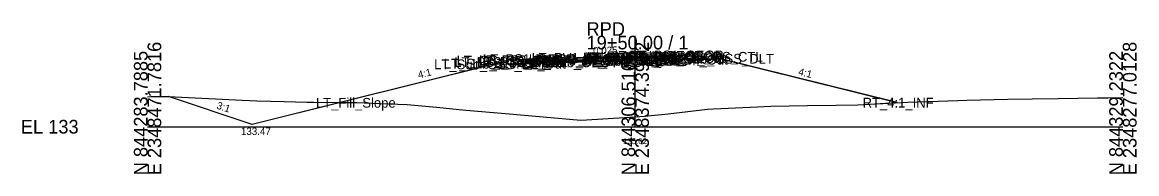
# Model space of a CAD drawing. Extents: x -26 to 2348536, y -510 to 844755.
# Drawn here: x -25.7 to 202.8, y 4490.3 to 4521.5 of the extents above; entities that cross this region are included whole.
import ezdxf

# ---------------------------------------------------------------- set-up
doc = ezdxf.new("R2010")
doc.units = 0
for name, color, linetype in [('Default', 7, 'Continuous'), ('Exist Cross Section Cell', 7, 'Continuous'), ('Exist XS Center Line Elevation Label', 7, 'Continuous'), ('Exist XS Ground Line', 7, 'Continuous'), ('Prop CMT Pvmt Course 1', 7, 'Continuous'), ('Prop CMT Pvmt Course 2', 7, 'Continuous'), ('Prop CMT Pvmt Course 3', 7, 'Continuous'), ('Prop CMT Pvmt Surface', 7, 'Continuous'), ('Prop CMT Pvmt Surface Shoulder', 7, 'Continuous'), ('Prop CMT Shld Paved Course 1', 7, 'Continuous'), ('Prop CMT Shld Paved Course 2', 7, 'Continuous'), ('Prop CMT Shld Paved Course 3', 7, 'Continuous'), ('Prop CMT Slope Grass', 7, 'Continuous'), ('Prop CMT Subgrade Earthwork', 7, 'Continuous'), ('Prop XS Ditch Standard Text', 7, 'Continuous'), ('Prop XS Earthwork Shape', 7, 'Continuous'), ('Prop XS SE Text', 7, 'Continuous'), ('Prop XS Side Slope Text', 7, 'Continuous'), ('Scratch_Level_0', 7, 'Continuous')]:
    doc.layers.add(name, color=color, linetype=linetype)

msp = doc.modelspace()

# ---------------------------------------------------------------- linework, layer by layer
at = {"layer": 'Exist Cross Section Cell'}
for p, q in [((100, 4500), (100, 4518.71)), ((0, 4500), (100, 4500)), ((100, 4500), (200, 4500))]:
    msp.add_line(p, q, dxfattribs=at)
at = {"layer": 'Exist XS Ground Line'}
msp.add_lwpolyline([(0, 4506.17), (0.69, 4506.2), (1.39, 4506.24), (2.65, 4506.23), (3.77, 4506.22), (4.26, 4506.21), (19.4, 4505.46), (22.4, 4505.31), (28.01, 4505.18), (32.67, 4505.06), (34.08, 4505.04), (42.94, 4504.95), (47.48, 4504.79), (53.2, 4504.55), (59.22, 4504.05), (65.24, 4503.37), (73.37, 4502.72), (88.88, 4501.34), (92.24, 4501.54), (100, 4502.02), (101.91, 4502.14), (106.73, 4502.68), (114.82, 4503.59), (116.03, 4503.66), (125.09, 4504.12), (127.84, 4504.2), (135.36, 4504.37), (141.24, 4504.45), (145.62, 4504.52), (154.63, 4505), (155.89, 4505.06), (160.05, 4505.21), (166.16, 4505.42), (168.02, 4505.44), (176.43, 4505.66), (181.42, 4505.72), (186.7, 4505.78), (194.81, 4505.92), (196.97, 4505.95), (200, 4505.99)], dxfattribs=at)
at = {"layer": 'Prop CMT Pvmt Course 1'}
for p, q in [((100, 4514.47), (88, 4514.17)), ((88, 4513.92), (100, 4514.22)), ((88, 4514.17), (88, 4513.92)), ((100, 4514.47), (104, 4514.57)), ((100, 4514.22), (100, 4514.47)), ((100, 4514.22), (100, 4514.47)), ((100, 4514.22), (100, 4514.35)), ((100, 4514.35), (100, 4514.35)), ((100, 4514.35), (100, 4514.22)), ((100, 4514.22), (100, 4514.35)), ((100, 4514.35), (100, 4514.35)), ((100, 4514.35), (100, 4514.22)), ((104, 4514.32), (100, 4514.22)), ((100, 4514.22), (100, 4514.22)), ((100, 4514.22), (100, 4514.22)), ((104, 4514.57), (104, 4514.32))]:
    msp.add_line(p, q, dxfattribs=at)
at = {"layer": 'Prop CMT Pvmt Course 2'}
for p, q in [((100, 4514.22), (88, 4513.92)), ((88, 4513.92), (88, 4513.59)), ((88, 4513.59), (100, 4513.89)), ((100, 4514.22), (104, 4514.32)), ((100, 4513.89), (100, 4514.22)), ((100, 4513.89), (100, 4514.22)), ((104, 4513.99), (100, 4513.89)), ((104, 4514.32), (104, 4513.99))]:
    msp.add_line(p, q, dxfattribs=at)
at = {"layer": 'Prop CMT Pvmt Course 3'}
for p, q in [((100, 4513.89), (88, 4513.59)), ((88, 4513.59), (88, 4513.25)), ((88, 4513.25), (100, 4513.55)), ((100, 4513.89), (104, 4513.99)), ((100, 4513.55), (100, 4513.89)), ((100, 4513.55), (100, 4513.89)), ((104, 4513.65), (100, 4513.55)), ((104, 4513.99), (104, 4513.65))]:
    msp.add_line(p, q, dxfattribs=at)
at = {"layer": 'Prop CMT Pvmt Surface'}
for q in [(88, 4514.17), (104, 4514.57)]:
    msp.add_line((100, 4514.47), q, dxfattribs=at)
at = {"layer": 'Prop CMT Pvmt Surface Shoulder'}
for p, q in [((88, 4514.17), (78, 4513.92)), ((104, 4514.57), (108, 4514.67))]:
    msp.add_line(p, q, dxfattribs=at)
at = {"layer": 'Prop CMT Shld Paved Course 1'}
for p, q in [((78, 4513.92), (77.74, 4513.66)), ((77.74, 4513.66), (88, 4513.92)), ((88, 4514.17), (78, 4513.92)), ((88, 4513.92), (88, 4514.17)), ((104, 4514.57), (108, 4514.67)), ((104, 4514.32), (104, 4514.57)), ((108.24, 4514.43), (104, 4514.32)), ((108, 4514.67), (108.24, 4514.43))]:
    msp.add_line(p, q, dxfattribs=at)
at = {"layer": 'Prop CMT Shld Paved Course 2'}
for p, q in [((77.74, 4513.66), (77.4, 4513.32)), ((77.4, 4513.32), (88, 4513.59)), ((88, 4513.92), (77.74, 4513.66)), ((88, 4513.59), (88, 4513.92)), ((104, 4514.32), (108.24, 4514.43)), ((104, 4513.99), (104, 4514.32)), ((108.57, 4514.1), (104, 4513.99)), ((108.24, 4514.43), (108.57, 4514.1))]:
    msp.add_line(p, q, dxfattribs=at)
at = {"layer": 'Prop CMT Shld Paved Course 3'}
for p, q in [((88, 4513.59), (77.4, 4513.32)), ((88, 4513.25), (88, 4513.59)), ((104, 4513.99), (108.57, 4514.1)), ((104, 4513.65), (104, 4513.99)), ((109.39, 4513.79), (104, 4513.65)), ((108.57, 4514.1), (109.07, 4514.11)), ((109.07, 4514.11), (109.39, 4513.79)), ((76.9, 4513.31), (76.56, 4512.97)), ((76.56, 4512.97), (88, 4513.25)), ((77.4, 4513.32), (76.9, 4513.31))]:
    msp.add_line(p, q, dxfattribs=at)
at = {"layer": 'Prop CMT Slope Grass'}
for p, q in [((74, 4513.6), (21.48, 4500.47)), ((78, 4513.92), (74, 4513.6)), ((108, 4514.67), (116, 4514.39)), ((116, 4514.39), (153.75, 4504.95)), ((21.48, 4500.47), (4.27, 4506.21))]:
    msp.add_line(p, q, dxfattribs=at)
at = {"layer": 'Prop CMT Subgrade Earthwork'}
for p, q in [((100, 4513.55), (88, 4513.25)), ((100, 4513.55), (104, 4513.65)), ((104, 4513.65), (109.39, 4513.79)), ((109.39, 4513.79), (117.59, 4513.99)), ((76.56, 4512.97), (70.9, 4512.83)), ((88, 4513.25), (76.56, 4512.97))]:
    msp.add_line(p, q, dxfattribs=at)
at = {"layer": 'Prop XS Earthwork Shape'}
for points in [[(88, 4513.25), (76.56, 4512.97), (70.9, 4512.83), (39.55, 4504.99), (42.94, 4504.95), (47.48, 4504.79), (53.2, 4504.55), (59.22, 4504.05), (65.24, 4503.37), (73.37, 4502.72), (88.88, 4501.34), (92.24, 4501.54), (100, 4502.02), (101.91, 4502.14), (106.73, 4502.68), (114.82, 4503.59), (116.03, 4503.66), (125.09, 4504.12), (127.84, 4504.2), (135.36, 4504.37), (141.24, 4504.45), (145.62, 4504.52), (153.75, 4504.95), (117.59, 4513.99), (109.39, 4513.79), (104, 4513.65), (100, 4513.55)], [(21.48, 4500.47), (4.27, 4506.21), (19.4, 4505.46), (22.4, 4505.31), (28.01, 4505.18), (32.67, 4505.06), (34.08, 4505.04), (39.55, 4504.99)]]:
    msp.add_lwpolyline(points, close=True, dxfattribs=at)

# ---------------------------------------------------------------- texts
at = {"layer": 'Default'}
msp.add_text('-', height=0.0001, dxfattribs=at).set_placement((0, 4500))
at = {"layer": 'Exist Cross Section Cell'}
for s, p in [('RPD', (90, 4518.71)), ('19+50.00 / 1', (90, 4515.91)), ('EL 133', (-26, 4498.6))]:
    msp.add_text(s, height=2.8, dxfattribs=at).set_placement(p)
for s, p in [('E 2348471.7816', (2.8, 4490)), ('E 2348374.3972', (102.8, 4490)), ('E 2348277.0128', (202.8, 4490)), ('N 844283.7885', (0, 4490)), ('N 844306.5103', (100, 4490)), ('N 844329.2322', (200, 4490))]:
    msp.add_text(s, height=2.8, rotation=90, dxfattribs=at).set_placement(p)
at = {"layer": 'Exist XS Center Line Elevation Label'}
msp.add_text('135.02', height=1.2, dxfattribs=at).set_placement((97.51, 4496.42))
at = {"layer": 'Prop XS Ditch Standard Text'}
msp.add_text('133.47', height=1.5, dxfattribs=at).set_placement((19.14, 4498.3))
at = {"layer": 'Prop XS SE Text'}
msp.add_text('0.025', height=1.5, rotation=1.4321, dxfattribs=at).set_placement((91.38, 4514.9))
at = {"layer": 'Prop XS Side Slope Text'}
for s, rotation, p in [('4:1', 14.0362, (55.63, 4509.91)), ('4:1', 345.9638, (133.35, 4510.68)), ('3:1', 341.5651, (14.03, 4503.76))]:
    msp.add_text(s, height=1.5, rotation=rotation, dxfattribs=at).set_placement(p)
at = {"layer": 'Scratch_Level_0'}
for s, p in [('LT_Sub_OSS_DLT', (58.77, 4511.84)), ('LT_Sub_Trench_Out', (60.76, 4511.97)), ('LT_PS3_Shelf_Out', (62.89, 4512.31)), ('LT_GS_OS_CTL', (63.37, 4512.6)), ('LT_PS3_OEOP', (67.64, 4512.32)), ('LT_PS2_OEOP', (67.98, 4512.66)), ('LT_PS1_OEOP', (68.8, 4512.92)), ('LT_Sub_OEOT', (78.08, 4512.25)), ('LT_PV2_OEOT', (78.17, 4512.92)), ('LT_PV3_OEOT', (78.17, 4512.59)), ('LT_PV1_OEOT', (78.74, 4513.17)), ('RT_Sub_OEEOP', (89.17, 4512.55)), ('LT_Sub_OEEOP', (89.21, 4512.55)), ('RT_PV2_OEEOP', (89.26, 4513.22)), ('RT_PV3_OEEOP', (89.26, 4512.89)), ('LT_PV2_OEEOP', (89.31, 4513.22)), ('LT_PV3_OEEOP', (89.31, 4512.89)), ('RT_PV1_OEEOP', (89.83, 4513.35)), ('LT_PV1_OEEOP', (89.87, 4513.35)), ('RT_PV2_IEEOP', (89.91, 4513.22)), ('LT_PV2_IEEOP', (89.95, 4513.22)), ('RT_PV1_IEEOP', (90.47, 4513.35)), ('LT_PV1_IEEOP', (90.52, 4513.35)), ('RT_Sub_Trench_Out', (93.55, 4512.79)), ('PV2_PGL', (93.91, 4513.22)), ('RT_Sub_OEOT', (94.03, 4512.65)), ('RT_PV2_OEOT', (94.13, 4513.32)), ('RT_PV3_OEOT', (94.13, 4512.99)), ('PV1_PGL', (94.47, 4513.47)), ('RT_PV1_OEOT', (94.69, 4513.57)), ('RT_PS3_Shelf_Out', (95.01, 4513.11)), ('RT_PS2_OEOP', (98.43, 4513.43)), ('RT_PS1_OEOP', (98.76, 4513.67)), ('RT_PS3_OEOP', (98.76, 4513.1)), ('RT_Sub_OSS_DLT', (104.94, 4512.99)), ('RT_GS_OS_CTL', (105.32, 4513.39)), ('LT_Fill_Slope', (34.52, 4503.92)), ('RT_4:1_INF', (146.63, 4503.95))]:
    msp.add_text(s, height=2, dxfattribs=at).set_placement(p)

doc.saveas('drawing.dxf')
